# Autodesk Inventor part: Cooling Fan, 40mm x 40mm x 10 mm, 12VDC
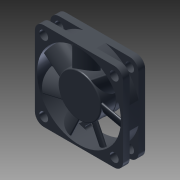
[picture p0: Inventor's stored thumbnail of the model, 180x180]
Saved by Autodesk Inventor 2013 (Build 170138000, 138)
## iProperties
Created: 2005-12
Part Number: Cooling Fan, 40mm x 40mm x 10 mm, 12VDC
Document SubType Name: Modeling
Designer: Autodesk Inc.
Density: 1 g/cm^3
Mass: 6.91726 g
Surface Area: 70.4562 cm^2
Volume: 6.91726 cm^3
Material: Allgemein
Company: Autodesk Inc.
GlobalPropertyList: <PropertyList/>
Title: Personal Computer
Author: Autodesk Inc.
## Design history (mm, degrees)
sketch "Sketch1"
  geometry: L1 (16, 16)-(-16, -16); L2 (-16, -20)-(16, -20); L3 (7.8, 6.258)-(16.726, -4.868); L4 (11.665, -0.957)-(16.878, -7.455); L5 (-0.321, 11.7)-(5.57, 17.591); L6 (16, 20)-(-16, 20); L7 (-20, 16)-(-20, -16); L8 (20, -16)-(20, 16); L9 (5.949, -8.038)-(-3.978, -16.962); L10 (-0.363, -11.695)-(-6.542, -17.25); L11 (-7.071, 7.071)-(3.015, 17.157); L12 (-11.636, 1.146)-(-16.808, 7.593); L13 (-8.737, -4.864)-(-16.683, 5.04); C1 r 2 at (16, -16); C2 r 2 at (16, 16); C3 r 2 at (-16, -16); C4 r 2 at (-16, 16); A1 r 10 centre (0, 0) between (5.949, -8.038) and (9.896, -1.439); A2 r 1 centre (10.885, -1.583) between (11.665, -0.957) and (9.896, -1.439); A3 r 19.013 centre (0, 0) between (18.478, -4.478) and (6.625, 17.821); A4 r 19.013 centre (0, 0) between (-3.493, -18.689) and (16.992, -8.529); A5 r 1 centre (17.506, -4.242) between (16.726, -4.868) and (18.478, -4.478); A6 r 4 centre (16, -16) between (16, -20) and (20, -16); A7 r 4 centre (16, 16) between (20, 16) and (16, 20); A8 r 1 centre (16.098, -8.081) between (16.981, -8.55) and (16.878, -7.455); A9 r 1 centre (-1.032, -10.952) between (-0.363, -11.695) and (-0.938, -9.956); A10 r 4 centre (-16, -16) between (-20, -16) and (-16, -20); A11 r 19.013 centre (0, 0) between (-18.433, 4.66) and (-7.611, -17.423); A12 r 10 centre (0, 0) between (-8.737, -4.864) and (-0.938, -9.956); A13 r 1 centre (-7.211, -16.506) between (-7.632, -17.413) and (-6.542, -17.25); A14 r 1 centre (-3.31, -17.706) between (-3.978, -16.962) and (-3.493, -18.689); A15 r 1 centre (0.387, 10.993) between (-0.321, 11.7) and (0.351, 9.994); A16 r 1 centre (6.277, 16.884) between (6.625, 17.821) and (5.57, 17.591); A17 r 1 centre (2.308, 17.864) between (3.015, 17.157) and (2.436, 18.856); A18 r 10 centre (0, 0) between (7.8, 6.258) and (0.351, 9.994); A19 r 4 centre (-16, 16) between (-16, 20) and (-20, 16); A20 r 1 centre (-10.856, 1.772) between (-11.636, 1.146) and (-9.869, 1.611); A21 r 10 centre (0, 0) between (-7.071, 7.071) and (-9.869, 1.611); A22 r 1 centre (-17.463, 4.415) between (-16.683, 5.04) and (-18.433, 4.66); A23 r 19.013 centre (0, 0) between (2.436, 18.856) and (-16.918, 8.675); A24 r 1 centre (-16.028, 8.219) between (-16.907, 8.696) and (-16.808, 7.593); 4 further points
  constraints: 51 point on circle, 28 centre point, 26 end point, 6 coincident, 2 midpoint, 1 horizontal alignment, 1 point on line, 1 vertical alignment
  dimensions: "d32" = 4 radius of A7; "d33" = 4 radius of A19; "d34" = 32 distance of L6.start L6.end; "d35" = 19.01265 radius of A23; "d36" = 4 diameter of C4; "d37" = 1 radius of A17; "d38" = 14.26379 distance of L11.start L11.end; "d39" = 10 radius of A21; "d40" = 1 radius of A20; "d41" = 8.26491 distance of L12.start L12.end; "d42" = 1 radius of A24; "d43" = 12.69773 distance of L13.start L13.end; "d44" = 1 radius of A22; "d45" = 19.01265 radius of A11; "d46" = 1 radius of A13; "d47" = 8.30896 distance of L10.start L10.end; "d48" = 1 radius of A9; "d49" = 10 radius of A12; "d50" = 4 diameter of C3; "d51" = 4 radius of A10; "d52" = 32 distance of L7.start L7.end; "d53" = 32 distance of L2.start L2.end; "d54" = 4 radius of A6; "d55" = 4 diameter of C1; "d56" = 32 distance of L8.start L8.end; "d57" = 4 diameter of C2; "d58" = 10 radius of A1; "d59" = 13.34845 distance of L9.start L9.end; "d60" = 1 radius of A14; "d61" = 19.01265 radius of A4; "d62" = 1 radius of A8; "d63" = 8.33025 distance of L4.start L4.end; "d64" = 1 radius of A2; "d65" = 19.01265 radius of A3; "d66" = 1 radius of A16; "d67" = 8.33025 distance of L5.start L5.end; "d68" = 1 radius of A15; "d69" = 10 radius of A18; "d70" = 14.26379 distance of L3.start L3.end; "d71" = 1 radius of A5; "d73" = 32 distance of C1.centre A7.centre; "d74" = 32 distance of C4.centre L1.start
extrude "Extrusion1" new body sketch "Sketch1" distance "d26" = 3; taper "d27" = 0 deg
sketch "Sketch5"
  geometry: L1 (16, -20)-(-16, -20) reference; L2 (20, 16)-(20, -16) reference; L3 (-16, 20)-(16, 20) reference; L4 (-20, -16)-(-20, 16) reference; C1 r 19.013 at (0, 0); A1 r 19.013 centre (0, 0) between (2.436, 18.856) and (-16.918, 8.675) reference; A2 r 20.627 centre (0, 0) between (-5.049, 20) and (-20, 5.049); A3 r 20.627 centre (0, 0) between (-20, -5.049) and (-5.049, -20); A4 r 20.627 centre (0, 0) between (5.049, -20) and (20, -5.049); A5 r 20.627 centre (0, 0) between (20, 5.049) and (5.049, 20)
  constraints: 8 point on circle, 8 point on line, 5 centre point, 2 coincident, 1 concentric
extrude "Extrusion4" join sketch "Sketch5" distance "d75" = 4; taper "d76" = 0 deg
sketch "Sketch6"
  geometry: L1 (-16, 20)-(16, 20); L2 (20, 16)-(20, -16); L3 (16, -20)-(-16, -20); L4 (-20, -16)-(-20, 16); C1 r 19.013 at (0, 0) reference; A1 r 4 centre (-16, 16) between (-16, 20) and (-20, 16) reference; A2 r 4 centre (16, 16) between (20, 16) and (16, 20) reference; A3 r 4 centre (16, -16) between (16, -20) and (20, -16) reference; A4 r 4 centre (-16, -16) between (-20, -16) and (-16, -20) reference; 8 further points
  constraints: 8 end point, 8 tangent, 3 perpendicular, 1 horizontal, 4 other
extrude "Extrusion5" join sketch "Sketch6" distance "d77" = 3; taper "d78" = 0 deg
sketch "Sketch7"
  geometry: L1 (7.071, 7.071)-(-3.015, 17.157) reference; L2 (16, -20)-(-16, -20) reference; L3 (-20, -16)-(-20, 16) reference; L4 (7.611, -17.423)-(9.188, -19); L5 (9.188, -19)-(10.688, -19); L6 (12.188, -19)-(12.475, -19); L7 (12.84, -18.158)-(10.607, -15.779); L8 (10.688, -20)-(12.188, -20); A1 r 19.013 centre (0, 0) between (7.611, -17.423) and (18.433, 4.66) reference; A2 r 1 centre (7.211, -16.506) between (6.542, -17.25) and (7.611, -17.423) reference; A3 r 10 centre (0, 0) between (9.869, 1.611) and (7.071, 7.071) reference; A4 r 0.5 centre (10.688, -19.5) between (10.688, -20) and (10.688, -19); A5 r 0.5 centre (12.188, -19.5) between (12.188, -19) and (12.188, -20); A6 r 0.5 centre (12.475, -18.5) between (12.475, -19) and (12.84, -18.158); A7 r 19.013 centre (0, 0) between (7.611, -17.423) and (10.607, -15.779)
  constraints: 11 point on circle, 10 end point, 7 tangent, 4 centre point, 2 point on line, 1 coincident, 1 collinear, 1 equal radius, 1 parallel, 1 perpendicular
  dimensions: "d79" = 1 distance between parallel lines of L2 L5; "d80" = 1.5 distance of L4.end L5.end; "d81" = 1.5 distance of A4.centre A5.centre
extrude "Extrusion6" cut sketch "Sketch7" distance "d83" = 3; taper "d84" = 0 deg
sketch "Sketch8"
  geometry: L1 (-12.84, -18.158)-(-11.725, -16.971) reference; L2 (-12.188, -20)-(-16, -20) reference; L3 (-8.83, -18.642)-(-9.188, -19) reference; L4 (-11.725, -16.971)-(-14.569, -20); L5 (-10.688, -20)-(16, -20) reference; L6 (-8.83, -18.642)-(-10.188, -20); L7 (-14.569, -20)-(-10.188, -20); L8 (-11.725, -16.971)-(-8.83, -18.642); A1 r 20.627 centre (0, 0) between (-11.725, -16.971) and (-8.83, -18.642) reference
  constraints: 8 end point, 3 collinear, 2 point on line
extrude "Extrusion7" cut sketch "Sketch8" distance "d85" = 1.5; taper "d86" = 0 deg
sketch "Sketch9" dims "d87" = 18
  geometry: L1 (0, -9)-(-7.036, -5.611); L2 (-7.036, -5.611)-(-8.774, 2.003); L3 (-8.774, 2.003)-(-3.905, 8.109); L4 (-3.905, 8.109)-(3.905, 8.109); L5 (3.905, 8.109)-(8.774, 2.003); L6 (8.774, 2.003)-(7.036, -5.611); L7 (7.036, -5.611)-(0, -9); A1 r 10 centre (0, 0) between (-8.737, -4.864) and (-0.938, -9.956) reference; 2 further points
  constraints: 14 end point, 2 coincident, 18 other
extrude "Extrusion8" join sketch "Sketch9" distance "d88" = 1.5; taper "d89" = 0 deg
sketch "Sketch10"
  geometry: L1 (7.81, 0)-(7.81, 7); L2 (7.81, 7)-(0, 7); L3 (0, 7)-(0, 0); L4 (0, 0)-(7.81, 0); L5 (0, 0.5)-(7.81, 0.5); L6 (0, 6.5)-(7.81, 6.5); A1 r 8.083 centre (7.81, -1.583) between (7.277, 6.482) and (0.21, 1.17); A2 r 7.083 centre (7.81, -1.583) between (7.343, 5.485) and (1.151, 0.83); A3 r 0.5 centre (7.31, 5.983) between (7.343, 5.485) and (7.277, 6.482); A4 r 0.5 centre (0.68, 1) between (0.21, 1.17) and (1.151, 0.83); 1 further point
  constraints: 12 end point, 8 point on circle, 7 tangent, 4 centre point, 4 point on line, 3 perpendicular, 2 coincident, 1 parallel
  dimensions: "d90" = 0.5 distance between parallel lines of L4 L5; "d92" = 7 distance of L2.end L3.end; "d93" = 7.80991 distance between parallel lines of L1 L3; "d94" = 1 radial gap between concentric circles of A2 A1
sketch "Sketch11"
  geometry: L1 (1.5, 7.81)-(-5.5, 7.81); L2 (-5.5, 7.81)-(-5.5, 0); L3 (1.5, 0)-(1.5, 7.81); L4 (1, 0)-(1, 7.81); L5 (-5, 0)-(-5, 7.81); L6 (-5.5, 0)-(1.5, 0); L7 (0, 7.81)-(0, 0) reference; L8 (1.5, 0)-(0, 0) reference; L9 (1.5, 7.81)-(1.5, 0) reference; L10 (1.5, 7.81)-(0, 7.81) reference; A1 r 0.5 centre (-4.483, 7.31) between (-3.985, 7.343) and (-4.982, 7.277); A2 r 7.083 centre (3.083, 7.81) between (-3.985, 7.343) and (0.67, 1.151); A3 r 8.083 centre (3.083, 7.81) between (-4.982, 7.277) and (0.33, 0.21); A4 r 0.5 centre (0.5, 0.68) between (0.33, 0.21) and (0.67, 1.151); 2 further points
  constraints: 12 end point, 8 point on circle, 7 tangent, 4 centre point, 4 point on line, 3 perpendicular, 2 coincident, 1 parallel
  dimensions: "d95" = 0.5 distance between parallel lines of L3 L4; "d96" = 7 distance of L2.end L3.start; "d97" = 7.80991 distance between parallel lines of L1 L6; "d98" = 1 radial gap between concentric circles of A2 A3
  node "Projected Loop1"
sketch "Sketch12"
  geometry: L1 (1.5, 7.81)-(0, 7.81); L2 (1.5, 7.81)-(-5.5, 7.81); L3 (-5, 0)-(-5, 7.81); L4 (-5.5, 7.81)-(-5.5, 0); L5 (0, 7.81)-(0, 0); L6 (1, 0)-(1, 7.81); L7 (1.5, 7.81)-(1.5, 0); L8 (1.5, 0)-(1.5, 7.81); L9 (-5.5, 0)-(1.5, 0); L10 (1.5, 0)-(0, 0); A1 r 7.083 centre (3.083, 7.81) between (-3.985, 7.343) and (0.67, 1.151); A2 r 8.083 centre (3.083, 7.81) between (-4.982, 7.277) and (0.33, 0.21); A3 r 0.5 centre (0.5, 0.68) between (0.33, 0.21) and (0.67, 1.151); A4 r 0.5 centre (-4.483, 7.31) between (-3.985, 7.343) and (-4.982, 7.277); 1 further point
  constraints: 20 end point, 8 point on circle, 7 tangent, 4 centre point, 4 point on line, 3 perpendicular, 2 coincident, 1 parallel
  dimensions: "d99" = 0.5 distance between parallel lines of L8 L6; "d100" = 7 distance of L4.end L7.end; "d101" = 7.80991 distance between parallel lines of L2 L9; "d102" = 1 radial gap between concentric circles of A1 A2
sketch "Sketch13"
  geometry: L1 (7.81, 1.5)-(0, 1.5); L2 (7.81, 1)-(0, 1); L3 (7.81, -5)-(0, -5); L4 (7.81, -5.5)-(7.81, 1.5); L5 (0, -5.5)-(7.81, -5.5); L6 (0, 1.5)-(0, -5.5); A1 r 0.5 centre (7.129, 0.5) between (7.6, 0.33) and (6.659, 0.67); A2 r 0.5 centre (0.5, -4.483) between (0.467, -3.985) and (0.533, -4.982); A3 r 7.083 centre (0, 3.083) between (0.467, -3.985) and (6.659, 0.67); A4 r 8.083 centre (0, 3.083) between (0.533, -4.982) and (7.6, 0.33); 1 further point
  constraints: 12 end point, 8 point on circle, 7 tangent, 4 centre point, 4 point on line, 3 perpendicular, 2 coincident, 1 parallel
  dimensions: "d103" = 0.5 distance between parallel lines of L1 L2; "d104" = 7 distance of L4.start L1.start; "d105" = 7.80991 distance between parallel lines of L6 L4; "d106" = 1 radial gap between concentric circles of A3 A4
sketch "Sketch14"
  geometry: L1 (0, -7.81)-(7, -7.81); L2 (6.5, 0)-(6.5, -7.81); L3 (7, -7.81)-(7, 0); L4 (0.5, 0)-(0.5, -7.81); L5 (0, 0)-(0, -7.81); L6 (7, 0)-(0, 0); A1 r 0.5 centre (5.983, -7.31) between (5.485, -7.343) and (6.482, -7.277); A2 r 7.083 centre (-1.583, -7.81) between (5.485, -7.343) and (0.83, -1.151); A3 r 8.083 centre (-1.583, -7.81) between (6.482, -7.277) and (1.17, -0.21); A4 r 0.5 centre (1, -0.68) between (1.17, -0.21) and (0.83, -1.151); 1 further point
  constraints: 12 end point, 8 point on circle, 7 tangent, 4 centre point, 4 point on line, 3 perpendicular, 2 coincident, 1 parallel
  dimensions: "d107" = 0.5 distance between parallel lines of L5 L4; "d108" = 7 distance of L3.end L5.start; "d109" = 7.80991 distance between parallel lines of L1 L6; "d110" = 1 radial gap between concentric circles of A2 A3
sketch "Sketch15"
  geometry: L1 (0, -7.81)-(1.5, -7.81); L2 (0, -7.81)-(7, -7.81); L3 (0.5, 0)-(0.5, -7.81); L4 (1.5, -7.81)-(1.5, 0); L5 (0, 0)-(1.5, 0); L6 (6.5, 0)-(6.5, -7.81); L7 (7, -7.81)-(7, 0); L8 (7, 0)-(0, 0); L9 (0, -7.81)-(0, 0); L10 (0, 0)-(0, -7.81); A1 r 0.5 centre (5.983, -7.31) between (5.485, -7.343) and (6.482, -7.277); A2 r 0.5 centre (1, -0.68) between (1.17, -0.21) and (0.83, -1.151); A3 r 7.083 centre (-1.583, -7.81) between (5.485, -7.343) and (0.83, -1.151); A4 r 8.083 centre (-1.583, -7.81) between (6.482, -7.277) and (1.17, -0.21); 1 further point
  constraints: 20 end point, 8 point on circle, 7 tangent, 4 centre point, 4 point on line, 3 coincident, 3 perpendicular, 1 parallel
  dimensions: "d111" = 0.5 distance between parallel lines of L10 L3; "d112" = 7 distance of L7.end L5.start; "d113" = 7.80991 distance between parallel lines of L2 L8; "d114" = 1 radial gap between concentric circles of A3 A4
sketch "Sketch16"
  geometry: L1 (7.81, 0)-(7.81, 7); L2 (0, 0.5)-(7.81, 0.5); L3 (0, 6.5)-(7.81, 6.5); L4 (7.81, 7)-(0, 7); L5 (0, 7)-(0, 0); L6 (0, 0)-(7.81, 0); A1 r 0.5 centre (7.31, 5.983) between (7.343, 5.485) and (7.277, 6.482); A2 r 0.5 centre (0.68, 1) between (0.21, 1.17) and (1.151, 0.83); A3 r 7.083 centre (7.81, -1.583) between (7.343, 5.485) and (1.151, 0.83); A4 r 8.083 centre (7.81, -1.583) between (7.277, 6.482) and (0.21, 1.17); 1 further point
  constraints: 12 end point, 8 point on circle, 7 tangent, 4 centre point, 4 point on line, 3 perpendicular, 1 coincident, 1 parallel, 1 vertical alignment
  dimensions: "d115" = 0.5 distance between parallel lines of L6 L2; "d116" = 7 distance of L4.end L5.end; "d117" = 7.80991 distance between parallel lines of L1 L5; "d118" = 1 radial gap between concentric circles of A3 A4
extrude "Extrusion9" join sketch "Sketch10" stored distance "d119" = 1; taper "d120" = 0 deg
extrude "Extrusion10" join sketch "Sketch11" stored distance "d121" = 1; taper "d122" = 0 deg
extrude "Extrusion11" join sketch "Sketch12" stored distance "d123" = 1; taper "d124" = 0 deg
extrude "Extrusion12" join sketch "Sketch13" stored distance "d125" = 1; taper "d126" = 0 deg
extrude "Extrusion13" join sketch "Sketch14" distance "d127" = 12; taper "d128" = 0 deg
extrude "Extrusion14" join sketch "Sketch15" distance "d129" = 11; taper "d130" = 0 deg
extrude "Extrusion15" join sketch "Sketch16" distance "d131" = 11; taper "d132" = 0 deg
sketch "Sketch17"
  geometry: C1 r 9.734 at (0, 0); A1 r 10 centre (0, 0) between (-8.737, -4.864) and (-0.938, -9.956) reference
  constraints: 1 centre point, 1 coincident
extrude "Extrusion16" join sketch "Sketch17" distance "d133" = 6.8; taper "d134" = 0 deg
fillet "Fillet1" dims "d135" = 0.5
workplane "Work Plane1"
sketch "Sketch18"
  geometry: L1 (3, 0)-(1.5, 0) reference; L2 (1.5, 3.097)-(3, 3.097) reference; L3 (3, 3.229)-(3, 0) reference; L4 (1.5, 1.414)-(1.5, 3.097) reference; L5 (1.5, 1.207)-(1.5, 0.354) reference; L6 (1.5, 0)-(1.5, 0.354) reference; C1 r 0.381 at (2.25, 1.168); C2 r 0.381 at (2.25, 1.93); 2 further points
  constraints: 2 centre point, 2 equal radius, 1 vertical alignment
  dimensions: "d137" = 0.762 diameter of C1
extrude "Extrusion17" cut sketch "Sketch18" distance "d138" = 11; taper "d139" = 0 deg
sketch "Sketch19"
  geometry: C1 r 19.013 at (0, 0) reference; C2 r 19.013 at (0, 0); C3 r 18.513 at (0, 0)
  constraints: 2 centre point, 2 coincident, 1 concentric
  dimensions: "d140" = 0.5 radial gap between concentric circles of C2 C3
extrude "Extrusion18" cut sketch "Sketch19" stored distance "d141" = 11; taper "d142" = 0 deg
node "+"
node "-"
body "Solid1"
sketch "Sketch20"
  geometry: 2 further points
  constraints: 1 horizontal alignment
sketch "Sketch21"
  geometry: 2 further points
  constraints: 1 horizontal alignment
other parameters: "d25" = 38.0253, "d82" = 45 deg, "d136" = 90 deg
